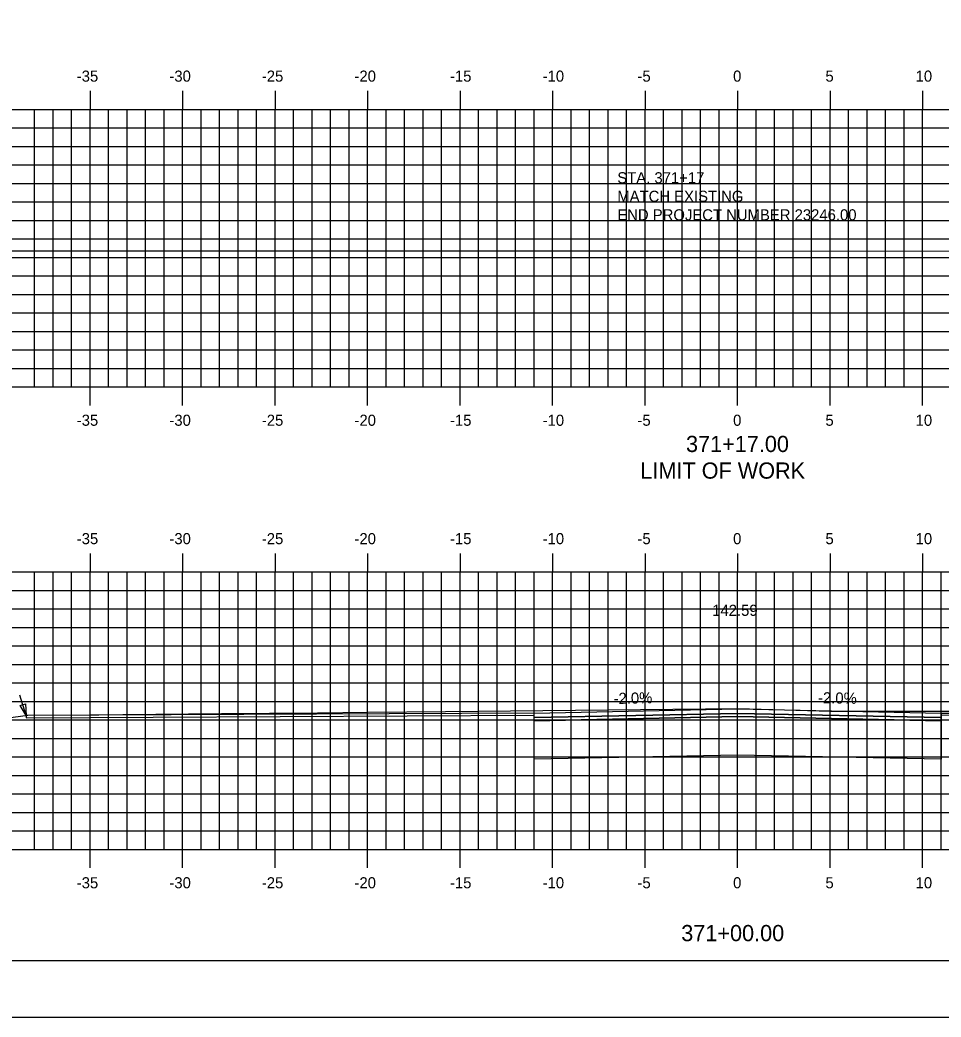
# Model space of a CAD drawing. Extents: x 1148299 to 1148469, y 608981 to 609091.
# Drawn here: x 1148342.9 to 1148392.7, y 608981.3 to 609035.2 of the extents above; entities that cross this region are included whole.
import ezdxf

# ---------------------------------------------------------------- set-up
doc = ezdxf.new("R2010")
doc.units = 0
for name, color, linetype in [('ANNOTATION', 7, 'Continuous'), ('BORDER', 7, 'Continuous'), ('D_Roadway_Centerline', 7, 'Continuous'), ('D_Roadway_Centerline_Text', 7, 'Continuous'), ('D_Roadway_Edge_TW', 7, 'Continuous'), ('D_Roadway_FinishedGrade', 7, 'Continuous'), ('D_Roadway_Pavement', 7, 'Continuous'), ('D_Roadway_SubGrade', 7, 'Continuous'), ('H_V ANNOTATION', 7, 'Continuous'), ('MAJOR', 7, 'Continuous'), ('MINOR', 7, 'Continuous'), ('PLOT BOUNDARY', 7, 'Continuous'), ('S_Roadway_Centerline', 7, 'Continuous')]:
    doc.layers.add(name, color=color, linetype=linetype)

msp = doc.modelspace()

# ---------------------------------------------------------------- linework, layer by layer
msp.add_lwpolyline([(1148370.724, 608997.71), (1148381.724, 608997.93), (1148392.724, 608997.71)])
at = {"layer": 'ANNOTATION'}
msp.add_line((1148343.264, 608997.583), (1148342.923, 608998.682), dxfattribs=at)
msp.add_lwpolyline([(1148343.229, 608998.2), (1148343.264, 608997.583), (1148342.943, 608998.112)], close=True, dxfattribs=at)
at = {"layer": 'BORDER'}
msp.add_lwpolyline([(1148306.724, 608984.335), (1148466.724, 608984.335), (1148466.724, 609089.335), (1148306.724, 609089.335)], close=True, dxfattribs=at)
at = {"layer": 'D_Roadway_Edge_TW'}
msp.add_lwpolyline([(1148370.724, 608997.46), (1148370.724, 608997.71), (1148381.724, 608997.93), (1148392.724, 608997.71), (1148392.724, 608997.46), (1148381.724, 608997.68)], close=True, dxfattribs=at)
at = {"layer": 'D_Roadway_FinishedGrade'}
for p, q in [((1148370.724, 608997.71), (1148343.264, 608997.583)), ((1148343.264, 608997.458), (1148370.724, 608997.585)), ((1148343.264, 608997.583), (1148343.264, 608997.458)), ((1148392.724, 608997.71), (1148421.324, 608997.449))]:
    msp.add_line(p, q, dxfattribs=at)
msp.add_lwpolyline([(1148421.324, 608997.449), (1148421.324, 608997.324), (1148392.724, 608997.585)], dxfattribs=at)
at = {"layer": 'D_Roadway_Pavement'}
msp.add_lwpolyline([(1148370.724, 608997.293), (1148370.724, 608997.46), (1148381.724, 608997.68), (1148392.724, 608997.46), (1148392.724, 608997.293), (1148381.724, 608997.513)], close=True, dxfattribs=at)
at = {"layer": 'D_Roadway_SubGrade'}
msp.add_lwpolyline([(1148370.724, 608995.21), (1148370.724, 608997.293), (1148381.724, 608997.513), (1148392.724, 608997.293), (1148392.724, 608995.21), (1148381.724, 608995.43)], close=True, dxfattribs=at)
at = {"layer": 'MAJOR'}
for p, q in [((1148346.724, 609031.337), (1148346.724, 609030.335)), ((1148351.724, 609031.337), (1148351.724, 609030.335)), ((1148356.724, 609031.337), (1148356.724, 609030.335)), ((1148361.724, 609031.337), (1148361.724, 609030.335)), ((1148366.724, 609031.337), (1148366.724, 609030.335)), ((1148371.724, 609031.337), (1148371.724, 609030.335)), ((1148376.724, 609031.337), (1148376.724, 609030.335)), ((1148381.724, 609031.337), (1148381.724, 609030.335)), ((1148386.724, 609031.337), (1148386.724, 609030.335)), ((1148391.724, 609031.337), (1148391.724, 609030.335)), ((1148311.724, 609030.335), (1148451.724, 609030.335)), ((1148311.724, 609030.335), (1148451.724, 609030.335)), ((1148346.724, 609015.335), (1148346.724, 609030.335)), ((1148351.724, 609015.335), (1148351.724, 609030.335)), ((1148356.724, 609015.335), (1148356.724, 609030.335)), ((1148361.724, 609015.335), (1148361.724, 609030.335)), ((1148366.724, 609015.335), (1148366.724, 609030.335)), ((1148371.724, 609015.335), (1148371.724, 609030.335)), ((1148376.724, 609015.335), (1148376.724, 609030.335)), ((1148381.724, 609015.335), (1148381.724, 609030.335)), ((1148386.724, 609015.335), (1148386.724, 609030.335)), ((1148391.724, 609015.335), (1148391.724, 609030.335)), ((1148311.724, 609025.335), (1148451.724, 609025.335)), ((1148311.724, 609020.335), (1148451.724, 609020.335)), ((1148311.724, 609015.335), (1148451.724, 609015.335)), ((1148311.724, 609015.335), (1148451.724, 609015.335)), ((1148346.724, 609014.333), (1148346.724, 609015.335)), ((1148351.724, 609014.333), (1148351.724, 609015.335)), ((1148356.724, 609014.333), (1148356.724, 609015.335)), ((1148361.724, 609014.333), (1148361.724, 609015.335)), ((1148366.724, 609014.333), (1148366.724, 609015.335)), ((1148371.724, 609014.333), (1148371.724, 609015.335)), ((1148376.724, 609014.333), (1148376.724, 609015.335)), ((1148381.724, 609014.333), (1148381.724, 609015.335)), ((1148386.724, 609014.333), (1148386.724, 609015.335)), ((1148391.724, 609014.333), (1148391.724, 609015.335)), ((1148346.724, 609006.337), (1148346.724, 609005.335)), ((1148351.724, 609006.337), (1148351.724, 609005.335)), ((1148356.724, 609006.337), (1148356.724, 609005.335)), ((1148361.724, 609006.337), (1148361.724, 609005.335)), ((1148366.724, 609006.337), (1148366.724, 609005.335)), ((1148371.724, 609006.337), (1148371.724, 609005.335)), ((1148376.724, 609006.337), (1148376.724, 609005.335)), ((1148381.724, 609006.337), (1148381.724, 609005.335)), ((1148386.724, 609006.337), (1148386.724, 609005.335)), ((1148391.724, 609006.337), (1148391.724, 609005.335)), ((1148311.724, 609005.335), (1148451.724, 609005.335)), ((1148311.724, 609005.335), (1148451.724, 609005.335)), ((1148346.724, 608990.335), (1148346.724, 609005.335)), ((1148351.724, 608990.335), (1148351.724, 609005.335)), ((1148356.724, 608990.335), (1148356.724, 609005.335)), ((1148361.724, 608990.335), (1148361.724, 609005.335)), ((1148366.724, 608990.335), (1148366.724, 609005.335)), ((1148371.724, 608990.335), (1148371.724, 609005.335)), ((1148376.724, 608990.335), (1148376.724, 609005.335)), ((1148381.724, 608990.335), (1148381.724, 609005.335)), ((1148386.724, 608990.335), (1148386.724, 609005.335)), ((1148391.724, 608990.335), (1148391.724, 609005.335)), ((1148311.724, 609000.335), (1148451.724, 609000.335)), ((1148311.724, 608995.335), (1148451.724, 608995.335)), ((1148311.724, 608990.335), (1148451.724, 608990.335)), ((1148311.724, 608990.335), (1148451.724, 608990.335)), ((1148346.724, 608989.333), (1148346.724, 608990.335)), ((1148351.724, 608989.333), (1148351.724, 608990.335)), ((1148356.724, 608989.333), (1148356.724, 608990.335)), ((1148361.724, 608989.333), (1148361.724, 608990.335)), ((1148366.724, 608989.333), (1148366.724, 608990.335)), ((1148371.724, 608989.333), (1148371.724, 608990.335)), ((1148376.724, 608989.333), (1148376.724, 608990.335)), ((1148381.724, 608989.333), (1148381.724, 608990.335)), ((1148386.724, 608989.333), (1148386.724, 608990.335)), ((1148391.724, 608989.333), (1148391.724, 608990.335))]:
    msp.add_line(p, q, dxfattribs=at)
at = {"layer": 'MINOR'}
for p, q in [((1148343.724, 609015.335), (1148343.724, 609030.335)), ((1148344.724, 609015.335), (1148344.724, 609030.335)), ((1148345.724, 609015.335), (1148345.724, 609030.335)), ((1148347.724, 609015.335), (1148347.724, 609030.335)), ((1148348.724, 609015.335), (1148348.724, 609030.335)), ((1148349.724, 609015.335), (1148349.724, 609030.335)), ((1148350.724, 609015.335), (1148350.724, 609030.335)), ((1148352.724, 609015.335), (1148352.724, 609030.335)), ((1148353.724, 609015.335), (1148353.724, 609030.335)), ((1148354.724, 609015.335), (1148354.724, 609030.335)), ((1148355.724, 609015.335), (1148355.724, 609030.335)), ((1148357.724, 609015.335), (1148357.724, 609030.335)), ((1148358.724, 609015.335), (1148358.724, 609030.335)), ((1148359.724, 609015.335), (1148359.724, 609030.335)), ((1148360.724, 609015.335), (1148360.724, 609030.335)), ((1148362.724, 609015.335), (1148362.724, 609030.335)), ((1148363.724, 609015.335), (1148363.724, 609030.335)), ((1148364.724, 609015.335), (1148364.724, 609030.335)), ((1148365.724, 609015.335), (1148365.724, 609030.335)), ((1148367.724, 609015.335), (1148367.724, 609030.335)), ((1148368.724, 609015.335), (1148368.724, 609030.335)), ((1148369.724, 609015.335), (1148369.724, 609030.335)), ((1148370.724, 609015.335), (1148370.724, 609030.335)), ((1148372.724, 609015.335), (1148372.724, 609030.335)), ((1148373.724, 609015.335), (1148373.724, 609030.335)), ((1148374.724, 609015.335), (1148374.724, 609030.335)), ((1148375.724, 609015.335), (1148375.724, 609030.335)), ((1148377.724, 609015.335), (1148377.724, 609030.335)), ((1148378.724, 609015.335), (1148378.724, 609030.335)), ((1148379.724, 609015.335), (1148379.724, 609030.335)), ((1148380.724, 609015.335), (1148380.724, 609030.335)), ((1148382.724, 609015.335), (1148382.724, 609030.335)), ((1148383.724, 609015.335), (1148383.724, 609030.335)), ((1148384.724, 609015.335), (1148384.724, 609030.335)), ((1148385.724, 609015.335), (1148385.724, 609030.335)), ((1148387.724, 609015.335), (1148387.724, 609030.335)), ((1148388.724, 609015.335), (1148388.724, 609030.335)), ((1148389.724, 609015.335), (1148389.724, 609030.335)), ((1148390.724, 609015.335), (1148390.724, 609030.335)), ((1148311.724, 609029.335), (1148451.724, 609029.335)), ((1148311.724, 609028.335), (1148451.724, 609028.335)), ((1148311.724, 609027.335), (1148451.724, 609027.335)), ((1148311.724, 609026.335), (1148451.724, 609026.335)), ((1148311.724, 609024.335), (1148451.724, 609024.335)), ((1148311.724, 609023.335), (1148451.724, 609023.335)), ((1148311.724, 609022.335), (1148451.724, 609022.335)), ((1148311.724, 609021.335), (1148451.724, 609021.335)), ((1148311.724, 609019.335), (1148451.724, 609019.335)), ((1148311.724, 609018.335), (1148451.724, 609018.335)), ((1148311.724, 609017.335), (1148451.724, 609017.335)), ((1148311.724, 609016.335), (1148451.724, 609016.335)), ((1148343.724, 608990.335), (1148343.724, 609005.335)), ((1148344.724, 608990.335), (1148344.724, 609005.335)), ((1148345.724, 608990.335), (1148345.724, 609005.335)), ((1148347.724, 608990.335), (1148347.724, 609005.335)), ((1148348.724, 608990.335), (1148348.724, 609005.335)), ((1148349.724, 608990.335), (1148349.724, 609005.335)), ((1148350.724, 608990.335), (1148350.724, 609005.335)), ((1148352.724, 608990.335), (1148352.724, 609005.335)), ((1148353.724, 608990.335), (1148353.724, 609005.335)), ((1148354.724, 608990.335), (1148354.724, 609005.335)), ((1148355.724, 608990.335), (1148355.724, 609005.335)), ((1148357.724, 608990.335), (1148357.724, 609005.335)), ((1148358.724, 608990.335), (1148358.724, 609005.335)), ((1148359.724, 608990.335), (1148359.724, 609005.335)), ((1148360.724, 608990.335), (1148360.724, 609005.335)), ((1148362.724, 608990.335), (1148362.724, 609005.335)), ((1148363.724, 608990.335), (1148363.724, 609005.335)), ((1148364.724, 608990.335), (1148364.724, 609005.335)), ((1148365.724, 608990.335), (1148365.724, 609005.335)), ((1148367.724, 608990.335), (1148367.724, 609005.335)), ((1148368.724, 608990.335), (1148368.724, 609005.335)), ((1148369.724, 608990.335), (1148369.724, 609005.335)), ((1148370.724, 608990.335), (1148370.724, 609005.335)), ((1148372.724, 608990.335), (1148372.724, 609005.335)), ((1148373.724, 608990.335), (1148373.724, 609005.335)), ((1148374.724, 608990.335), (1148374.724, 609005.335)), ((1148375.724, 608990.335), (1148375.724, 609005.335)), ((1148377.724, 608990.335), (1148377.724, 609005.335)), ((1148378.724, 608990.335), (1148378.724, 609005.335)), ((1148379.724, 608990.335), (1148379.724, 609005.335)), ((1148380.724, 608990.335), (1148380.724, 609005.335)), ((1148382.724, 608990.335), (1148382.724, 609005.335)), ((1148383.724, 608990.335), (1148383.724, 609005.335)), ((1148384.724, 608990.335), (1148384.724, 609005.335)), ((1148385.724, 608990.335), (1148385.724, 609005.335)), ((1148387.724, 608990.335), (1148387.724, 609005.335)), ((1148388.724, 608990.335), (1148388.724, 609005.335)), ((1148389.724, 608990.335), (1148389.724, 609005.335)), ((1148390.724, 608990.335), (1148390.724, 609005.335)), ((1148392.724, 608990.335), (1148392.724, 609005.335)), ((1148311.724, 609004.335), (1148451.724, 609004.335)), ((1148311.724, 609003.335), (1148451.724, 609003.335)), ((1148311.724, 609002.335), (1148451.724, 609002.335)), ((1148311.724, 609001.335), (1148451.724, 609001.335)), ((1148311.724, 608999.335), (1148451.724, 608999.335)), ((1148311.724, 608998.335), (1148451.724, 608998.335)), ((1148311.724, 608997.335), (1148451.724, 608997.335)), ((1148311.724, 608996.335), (1148451.724, 608996.335)), ((1148311.724, 608994.335), (1148451.724, 608994.335)), ((1148311.724, 608993.335), (1148451.724, 608993.335)), ((1148311.724, 608992.335), (1148451.724, 608992.335)), ((1148311.724, 608991.335), (1148451.724, 608991.335))]:
    msp.add_line(p, q, dxfattribs=at)
at = {"layer": 'PLOT BOUNDARY'}
msp.add_lwpolyline([(1148298.63, 608981.276), (1148468.63, 608981.276), (1148468.63, 609091.276), (1148298.63, 609091.276)], close=True, dxfattribs=at)
at = {"layer": 'S_Roadway_Centerline'}
for points in [[(1148338.577, 609022.693), (1148379.772, 609022.685), (1148380.206, 609022.687), (1148380.419, 609022.688), (1148380.728, 609022.69), (1148380.844, 609022.691), (1148381.022, 609022.692), (1148381.153, 609022.694), (1148381.221, 609022.694), (1148381.327, 609022.695), (1148381.724, 609022.699), (1148381.85, 609022.696), (1148393.432, 609022.668)], [(1148311.724, 608997.456), (1148324.779, 608996.299), (1148330.75, 608996.073), (1148331.736, 608996.041), (1148336.482, 608996.659), (1148343.351, 608997.595), (1148346.718, 608997.619), (1148353.827, 608997.677), (1148359.018, 608997.725), (1148361.738, 608997.751), (1148365.941, 608997.793), (1148381.74, 608997.946), (1148386.77, 608997.817), (1148393.486, 608997.801)]]:
    msp.add_lwpolyline(points, dxfattribs=at)

# ---------------------------------------------------------------- texts
at = {"layer": 'ANNOTATION'}
for s, p in [('STA. 371+17', (1148375.223, 609026.342)), ('MATCH EXISTING', (1148375.223, 609025.34)), ('END PROJECT NUMBER 23246.00', (1148375.223, 609024.338))]:
    msp.add_text(s, height=0.6, dxfattribs=at).set_placement(p)
for rotation, p in [(1.1458, (1148375.027, 608998.196)), (358.8542, (1148386.067, 608998.243))]:
    msp.add_text('-2.0%', height=0.6, rotation=rotation, dxfattribs=at).set_placement(p)
at = {"layer": 'D_Roadway_Centerline'}
for s, p in [('C', (1148381.718, 609022.698)), ('L', (1148381.724, 609022.691)), ('C', (1148381.718, 608997.93)), ('L', (1148381.724, 608997.923))]:
    msp.add_text(s, height=0.0146, dxfattribs=at).set_placement(p)
at = {"layer": 'D_Roadway_Centerline_Text'}
msp.add_text('142.59', height=0.6, dxfattribs=at).set_placement((1148380.354, 609002.962))
at = {"layer": 'H_V ANNOTATION'}
for s, height, p in [('-35', 0.6, (1148346.004, 609031.835)), ('-30', 0.6, (1148351.012, 609031.835)), ('-25', 0.6, (1148356.009, 609031.835)), ('-20', 0.6, (1148361.017, 609031.835)), ('-15', 0.6, (1148366.18, 609031.835)), ('-10', 0.6, (1148371.188, 609031.835)), ('-5', 0.6, (1148376.314, 609031.835)), ('0', 0.6, (1148381.483, 609031.835)), ('5', 0.6, (1148386.475, 609031.835)), ('10', 0.6, (1148391.349, 609031.835)), ('-35', 0.6, (1148346.004, 609013.235)), ('-30', 0.6, (1148351.012, 609013.235)), ('-25', 0.6, (1148356.009, 609013.235)), ('-20', 0.6, (1148361.017, 609013.235)), ('-15', 0.6, (1148366.18, 609013.235)), ('-10', 0.6, (1148371.188, 609013.235)), ('-5', 0.6, (1148376.314, 609013.235)), ('0', 0.6, (1148381.483, 609013.235)), ('5', 0.6, (1148386.475, 609013.235)), ('10', 0.6, (1148391.349, 609013.235)), ('371+17.00', 0.875, (1148378.938, 609011.817)), ('LIMIT OF WORK ', 0.87498, (1148376.47, 609010.378)), ('-35', 0.6, (1148346.004, 609006.835)), ('-30', 0.6, (1148351.012, 609006.835)), ('-25', 0.6, (1148356.009, 609006.835)), ('-20', 0.6, (1148361.017, 609006.835)), ('-15', 0.6, (1148366.18, 609006.835)), ('-10', 0.6, (1148371.188, 609006.835)), ('-5', 0.6, (1148376.314, 609006.835)), ('0', 0.6, (1148381.483, 609006.835)), ('5', 0.6, (1148386.475, 609006.835)), ('10', 0.6, (1148391.349, 609006.835)), ('-35', 0.6, (1148346.004, 608988.235)), ('-30', 0.6, (1148351.012, 608988.235)), ('-25', 0.6, (1148356.009, 608988.235)), ('-20', 0.6, (1148361.017, 608988.235)), ('-15', 0.6, (1148366.18, 608988.235)), ('-10', 0.6, (1148371.188, 608988.235)), ('-5', 0.6, (1148376.314, 608988.235)), ('0', 0.6, (1148381.483, 608988.235)), ('5', 0.6, (1148386.475, 608988.235)), ('10', 0.6, (1148391.349, 608988.235)), ('371+00.00', 0.875, (1148378.68, 608985.378))]:
    msp.add_text(s, height=height, dxfattribs=at).set_placement(p)
at = {"layer": 'S_Roadway_Centerline'}
for s, p in [('C', (1148381.719, 609022.699)), ('L', (1148381.724, 609022.692)), ('C', (1148381.735, 608997.946)), ('L', (1148381.74, 608997.939))]:
    msp.add_text(s, height=0.0146, dxfattribs=at).set_placement(p)

doc.saveas('drawing.dxf')
